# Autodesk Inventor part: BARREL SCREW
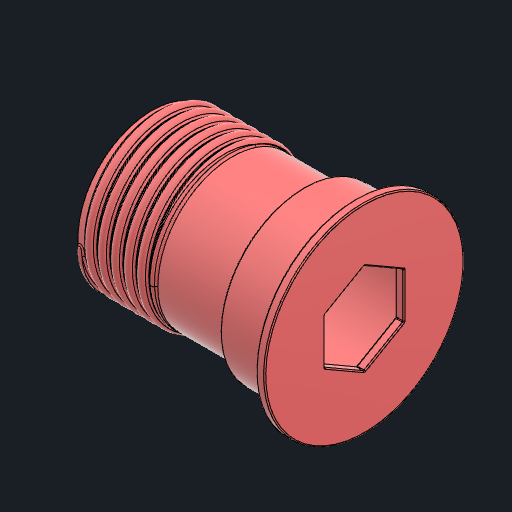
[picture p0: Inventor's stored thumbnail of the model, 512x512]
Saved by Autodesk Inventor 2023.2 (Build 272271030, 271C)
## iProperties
Created: 2022-12
Part Number: BARREL SCREW
Material: Generic
Document SubType Name: Modeling
Designer: AR
Mass: 16.1548 g
Surface Area: 132.665 cm^2
Volume: 16.1548 cm^3
Density: 1 g/cm^3
Appearance: Smooth - Light Orange
Author: AR
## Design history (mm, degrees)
derived "_2 SPOOL CORD WRAP MP.ipt"
feature "PRUSA BARREL SCREW::_2 SPOOL CORD WRAP MP.ipt" dims "d0" = 10
tag "TaggingFeature1"
node "PRUSA BARREL SCREW"
